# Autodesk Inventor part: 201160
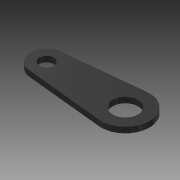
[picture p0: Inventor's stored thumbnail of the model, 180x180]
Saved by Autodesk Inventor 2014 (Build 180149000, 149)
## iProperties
Created: 2007-10
Part Number: 201160
Document SubType Name: Modeling
Designer: TH
Density: 7.85 g/cm^3
Mass: 40.6964 g
Surface Area: 38.5523 cm^2
Volume: 5.18426 cm^3
Material: Steel
Description: PIVOT PLATE
Appearance: Rubber - Black - Version 1.1
Component Category: Lower Component
Author: TH
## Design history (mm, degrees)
sketch "Sketch1"
  geometry: L1 (0, 0)-(-49, 0); L2 (-50.02, 9.948)-(-1.531, 14.922); L3 (-50.02, -9.948)-(-1.531, -14.922); A1 r 15 centre (0, 0) between (-1.531, -14.922) and (-1.531, 14.922); A2 r 10 centre (-49, 0) between (-50.02, 9.948) and (-50.02, -9.948); 1 further point
  constraints: 6 end point, 4 point on circle, 4 tangent, 2 centre point, 2 coincident, 1 horizontal
  dimensions: "d0" = 20 diameter of A2; "d1" = 30 diameter of A1; "d2" = 49 distance of point (0, 0) L1.end
extrude "Extrusion1" new body sketch "Sketch1" stored distance "d3" = 3.5; taper "d4" = 0 deg
sketch "Sketch2"
  geometry: A1 r 15 centre (0, 0) between (-1.531, -14.922) and (-1.531, 14.922) reference
hole "Hole1" sketch "Sketch2" at (0, 0) diameter "d5" = 15.84; stored, may be unused: countersink angle "d9" = 90 deg, drill point angle "d11" = 118 deg; dims "d6" = 6, "d7" = 4, "d8" = 2, "d10" = 8
sketch "Sketch3"
  geometry: A1 r 10 centre (-49, 0) between (-50.02, 9.948) and (-50.02, -9.948) reference
hole "Hole2" sketch "Sketch3" at (-49, 0) diameter "d12" = 9; stored, may be unused: countersink angle "d16" = 90 deg, drill point angle "d18" = 118 deg; dims "d13" = 6, "d14" = 4, "d15" = 2, "d17" = 8
body "Solid1"
